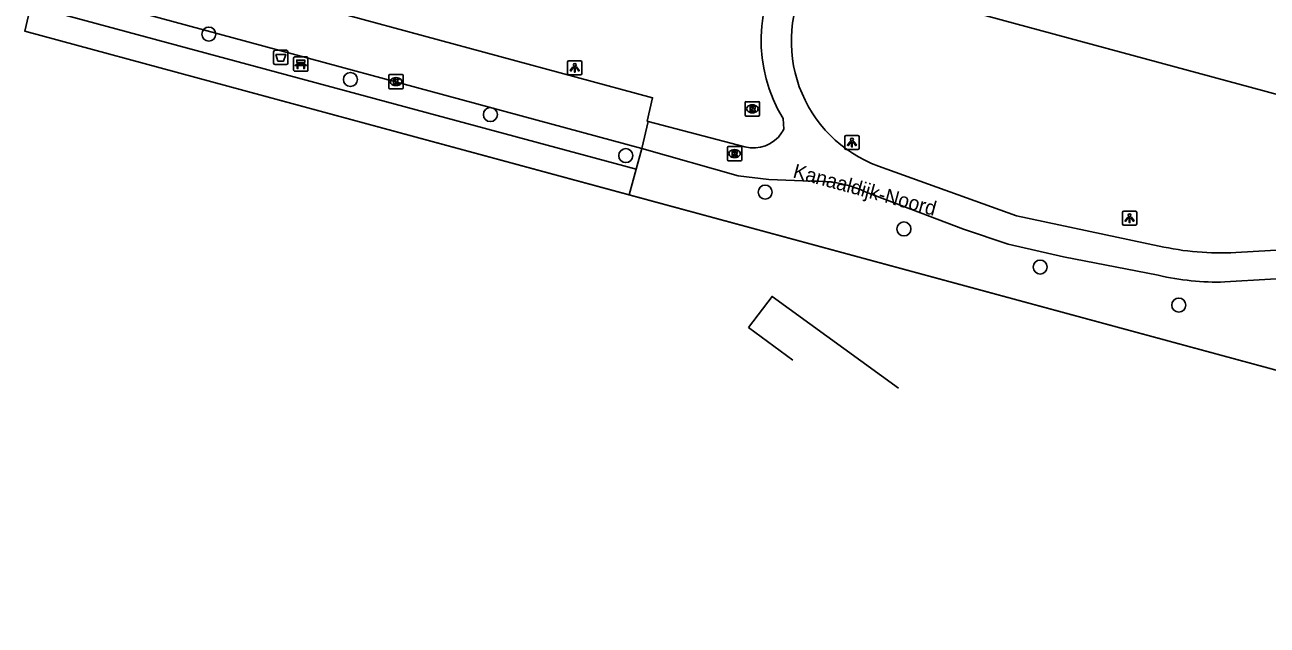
# Model space of a CAD drawing. Extents: x 161772 to 163123, y 383092 to 383917.
# Drawn here: x 161987 to 162073.6, y 383107.9 to 383149.8 of the extents above; entities that cross this region are included whole.
import ezdxf

# ---------------------------------------------------------------- set-up
doc = ezdxf.new("R2010")
doc.units = 0
for name, color, linetype in [('IMGEO_Afvalbak', 7, 'Continuous'), ('IMGEO_Bank', 7, 'Continuous'), ('IMGEO_Boom', 7, 'Continuous'), ('IMGEO_Kademuur', 7, 'Continuous'), ('IMGEO_Kolk', 7, 'Continuous'), ('IMGEO_Lichtpunt', 7, 'Continuous'), ('IMGEO_Openbare_ruimte_label', 7, 'Continuous'), ('IMGEO_Pand', 7, 'Continuous'), ('IMGEO_Rioolput', 7, 'Continuous'), ('IMGEO_Voetpad_halfverhard', 7, 'Continuous'), ('IMGEO_Voetpad_open', 7, 'Continuous'), ('IMGEO_Waterloop', 7, 'Continuous')]:
    doc.layers.add(name, color=color, linetype=linetype)

msp = doc.modelspace()

# ---------------------------------------------------------------- linework, layer by layer
at = {"layer": 'IMGEO_Afvalbak'}
for p, q in [((162004.321, 383147.103), (162004.321, 383147.903)), ((162004.321, 383147.903), (162004.321, 383147.103)), ((162004.421, 383148.003), (162005.211, 383148.003)), ((162005.211, 383148.003), (162004.421, 383148.003)), ((162005.311, 383147.903), (162005.311, 383147.103)), ((162005.311, 383147.103), (162005.311, 383147.903)), ((162005.211, 383147.003), (162004.421, 383147.003)), ((162004.421, 383147.003), (162005.211, 383147.003))]:
    msp.add_line(p, q, dxfattribs=at)
msp.add_lwpolyline([(162004.464, 383147.717), (162005.168, 383147.717), (162005.019, 383147.247), (162004.613, 383147.247), (162004.464, 383147.717)], dxfattribs=at)
for centre, start, end in [((162004.421, 383147.903), 90, 180), ((162004.421, 383147.903), 90, 180), ((162005.211, 383147.903), 0, 90), ((162005.211, 383147.903), 360, 90), ((162004.421, 383147.103), 180, 270), ((162004.421, 383147.103), 180, 270), ((162005.211, 383147.103), 270, 0), ((162005.211, 383147.103), 270, 0)]:
    msp.add_arc(centre, 0.1, start, end, dxfattribs=at)
at = {"layer": 'IMGEO_Bank'}
for p, q in [((162005.789, 383147.542), (162006.63, 383147.542)), ((162006.63, 383147.542), (162005.789, 383147.542)), ((162006.714, 383147.467), (162006.714, 383146.626)), ((162006.714, 383146.626), (162006.714, 383147.467)), ((162005.714, 383146.617), (162005.714, 383147.458)), ((162005.714, 383147.458), (162005.714, 383146.617)), ((162006.411, 383146.94), (162006.018, 383146.94)), ((162006.023, 383147.048), (162006.023, 383147.154)), ((162006.067, 383147.154), (162006.067, 383147.048)), ((162006.355, 383147.16), (162006.073, 383147.16)), ((162006.073, 383147.042), (162006.355, 383147.042)), ((162006.361, 383147.048), (162006.361, 383147.154)), ((162006.405, 383147.154), (162006.405, 383147.048)), ((162006.639, 383146.542), (162005.798, 383146.542)), ((162005.798, 383146.542), (162006.639, 383146.542))]:
    msp.add_line(p, q, dxfattribs=at)
for points in [[(162005.961, 383146.94), (162005.819, 383146.94), (162005.931, 383147.042), (162006.017, 383147.042)], [(162006.017, 383147.16), (162005.931, 383147.16), (162005.931, 383147.321), (162006.494, 383147.321), (162006.494, 383147.16), (162006.411, 383147.16)], [(162006.011, 383146.933), (162006.011, 383146.726), (162005.968, 383146.726), (162005.968, 383146.933)], [(162006.411, 383147.042), (162006.494, 383147.042), (162006.606, 383146.94), (162006.467, 383146.94)], [(162006.461, 383146.933), (162006.461, 383146.726), (162006.417, 383146.726), (162006.417, 383146.933)]]:
    msp.add_lwpolyline(points, dxfattribs=at)
for centre, radius, start, end in [((162005.792, 383147.464), 0.0779, 92.4484, 184.28452), ((162005.792, 383147.464), 0.0779, 92.4484, 184.28452), ((162006.636, 383147.464), 0.0779, 2.4484, 94.28452), ((162006.636, 383147.464), 0.0779, 2.4484, 94.28452), ((162005.792, 383146.62), 0.0779, 182.4484, 274.28452), ((162005.792, 383146.62), 0.0779, 182.4484, 274.28452), ((162005.961, 383146.933), 0.00671, 2.89567, 87.10433), ((162006.018, 383146.933), 0.00671, 92.89567, 177.10433), ((162006.016, 383147.153), 0.00671, 2.89567, 87.10433), ((162006.016, 383147.049), 0.00671, 272.89567, 357.10433), ((162006.073, 383147.153), 0.00671, 92.89567, 177.10433), ((162006.073, 383147.049), 0.00671, 182.89567, 267.10433), ((162006.355, 383147.153), 0.00671, 2.89567, 87.10433), ((162006.355, 383147.049), 0.00671, 272.89567, 357.10433), ((162006.412, 383147.153), 0.00671, 92.89567, 177.10433), ((162006.412, 383147.049), 0.00671, 182.89567, 267.10433), ((162006.41, 383146.933), 0.00671, 2.89567, 87.10433), ((162006.467, 383146.933), 0.00671, 92.89567, 177.10433), ((162006.636, 383146.62), 0.0779, 272.4484, 4.28452), ((162006.636, 383146.62), 0.0779, 272.4484, 4.28452)]:
    msp.add_arc(centre, radius, start, end, dxfattribs=at)
at = {"layer": 'IMGEO_Boom'}
for centre in [(161999.799, 383149.13), (162009.672, 383145.967), (162019.431, 383143.518), (162028.874, 383140.66), (162038.592, 383138.117), (162048.27, 383135.548), (162057.766, 383132.895), (162067.433, 383130.242)]:
    msp.add_circle(centre, 0.489, dxfattribs=at)
at = {"layer": 'IMGEO_Kademuur'}
msp.add_lwpolyline([(162139.881, 383107.934), (162112.481, 383115.352), (162000, 383145.804), (161986.972, 383149.331), (161990.33, 383163.776)], dxfattribs=at)
at = {"layer": 'IMGEO_Kolk'}
for p, q in [((162012.351, 383145.391), (162012.351, 383146.243)), ((162012.426, 383146.317), (162013.278, 383146.317)), ((162012.839, 383146.097), (162012.864, 383146.097)), ((162013.352, 383146.243), (162013.352, 383145.391)), ((162013.278, 383145.317), (162012.426, 383145.317)), ((162012.862, 383145.537), (162012.837, 383145.537))]:
    msp.add_line(p, q, dxfattribs=at)
for points in [[(162012.351, 383145.391), (162012.351, 383146.243)], [(162012.426, 383146.317), (162013.278, 383146.317)], [(162012.672, 383146.017), (162012.795, 383146.017), (162012.795, 383145.866), (162012.925, 383146.017), (162013.089, 383146.017), (162012.943, 383145.866), (162013.096, 383145.617), (162012.944, 383145.617), (162012.859, 383145.781), (162012.795, 383145.714), (162012.795, 383145.617), (162012.672, 383145.617), (162012.672, 383146.017)], [(162013.352, 383146.243), (162013.352, 383145.391)], [(162013.278, 383145.317), (162012.426, 383145.317)]]:
    msp.add_lwpolyline(points, dxfattribs=at)
for centre, start, end in [((162012.428, 383146.241), 91.55205, 178.44795), ((162012.428, 383146.241), 91.55205, 178.44795), ((162013.276, 383146.241), 1.55205, 88.44795), ((162013.276, 383146.241), 1.55205, 88.44795), ((162012.428, 383145.393), 181.55205, 268.44795), ((162012.428, 383145.393), 181.55205, 268.44795), ((162013.276, 383145.393), 271.55205, 358.44795), ((162013.276, 383145.393), 271.55205, 358.44795)]:
    msp.add_arc(centre, 0.0765, start, end, dxfattribs=at)
for centre, major_axis, ratio, start_param, end_param in [((162012.838, 383145.817), (-0.387, 0.002), 0.722429, 4.712389, 7.853982), ((162012.863, 383145.817), (-0.39, 0.002), 0.717154, 1.570796, 4.712389)]:
    msp.add_ellipse(centre, major_axis=major_axis, ratio=ratio, start_param=start_param, end_param=end_param, dxfattribs=at)
at = {"layer": 'IMGEO_Lichtpunt'}
for p, q in [((162024.818, 383147.184), (162024.818, 383146.377)), ((162024.818, 383147.184), (162024.818, 383146.377)), ((162025.72, 383147.279), (162024.912, 383147.279)), ((162025.72, 383147.279), (162024.912, 383147.279)), ((162025.814, 383146.377), (162025.814, 383147.184)), ((162025.814, 383146.377), (162025.814, 383147.184)), ((162024.912, 383146.283), (162025.72, 383146.283)), ((162024.912, 383146.283), (162025.72, 383146.283)), ((162044.145, 383141.978), (162044.145, 383141.171)), ((162044.145, 383141.978), (162044.145, 383141.171)), ((162045.047, 383142.073), (162044.239, 383142.073)), ((162045.047, 383142.073), (162044.239, 383142.073)), ((162045.141, 383141.171), (162045.141, 383141.978)), ((162045.141, 383141.171), (162045.141, 383141.978)), ((162044.239, 383141.077), (162045.047, 383141.077)), ((162044.239, 383141.077), (162045.047, 383141.077)), ((162063.503, 383136.704), (162063.503, 383135.897)), ((162063.503, 383136.704), (162063.503, 383135.897)), ((162064.405, 383136.799), (162063.597, 383136.799)), ((162064.405, 383136.799), (162063.597, 383136.799)), ((162064.499, 383135.897), (162064.499, 383136.704)), ((162064.499, 383135.897), (162064.499, 383136.704)), ((162063.597, 383135.803), (162064.405, 383135.803)), ((162063.597, 383135.803), (162064.405, 383135.803))]:
    msp.add_line(p, q, dxfattribs=at)
for points in [[(162025.192, 383146.848), (162025.231, 383146.82), (162025.043, 383146.558), (162025.005, 383146.585), (162025.192, 383146.848)], [(162025.294, 383146.8), (162025.341, 383146.8), (162025.341, 383146.478), (162025.294, 383146.478), (162025.294, 383146.8)], [(162025.404, 383146.82), (162025.442, 383146.847), (162025.629, 383146.585), (162025.59, 383146.557), (162025.404, 383146.82)], [(162044.519, 383141.642), (162044.558, 383141.614), (162044.37, 383141.352), (162044.332, 383141.379), (162044.519, 383141.642)], [(162044.621, 383141.594), (162044.668, 383141.594), (162044.668, 383141.272), (162044.621, 383141.272), (162044.621, 383141.594)], [(162044.731, 383141.614), (162044.769, 383141.641), (162044.956, 383141.379), (162044.917, 383141.351), (162044.731, 383141.614)], [(162063.877, 383136.368), (162063.916, 383136.34), (162063.728, 383136.078), (162063.69, 383136.105), (162063.877, 383136.368)], [(162063.979, 383136.32), (162064.026, 383136.32), (162064.026, 383135.998), (162063.979, 383135.998), (162063.979, 383136.32)], [(162064.089, 383136.34), (162064.127, 383136.367), (162064.314, 383136.105), (162064.275, 383136.077), (162064.089, 383136.34)]]:
    msp.add_lwpolyline(points, dxfattribs=at)
for centre in [(162025.317, 383146.982), (162044.644, 383141.776), (162064.002, 383136.502)]:
    msp.add_circle(centre, 0.0994, dxfattribs=at)
for centre, start, end in [((162024.912, 383147.184), 90, 180), ((162024.912, 383147.184), 90, 180), ((162025.72, 383147.184), 0, 90), ((162025.72, 383147.184), 0, 90), ((162024.912, 383146.377), 180, 270), ((162024.912, 383146.377), 180, 270), ((162025.72, 383146.377), 270, 0), ((162025.72, 383146.377), 270, 360), ((162044.239, 383141.978), 90, 180), ((162044.239, 383141.978), 90, 180), ((162045.047, 383141.978), 0, 90), ((162045.047, 383141.978), 0, 90), ((162044.239, 383141.171), 180, 270), ((162044.239, 383141.171), 180, 270), ((162045.047, 383141.171), 270, 0), ((162045.047, 383141.171), 270, 360), ((162063.597, 383136.704), 90, 180), ((162063.597, 383136.704), 90, 180), ((162064.405, 383136.704), 0, 90), ((162064.405, 383136.704), 0, 90), ((162063.597, 383135.897), 180, 270), ((162063.597, 383135.897), 180, 270), ((162064.405, 383135.897), 270, 0), ((162064.405, 383135.897), 270, 360)]:
    msp.add_arc(centre, 0.0946, start, end, dxfattribs=at)
at = {"layer": 'IMGEO_Pand'}
msp.add_lwpolyline([(162090.04, 383147.373), (162088.311, 383141.123), (162051.363, 383151.118), (162045.642, 383156.284)], dxfattribs=at)
at = {"layer": 'IMGEO_Rioolput'}
for p, q in [((162037.199, 383143.495), (162037.199, 383144.347)), ((162037.274, 383144.421), (162038.126, 383144.421)), ((162037.687, 383144.201), (162037.712, 383144.201)), ((162038.2, 383144.347), (162038.2, 383143.495)), ((162038.126, 383143.421), (162037.274, 383143.421)), ((162037.71, 383143.641), (162037.685, 383143.641)), ((162035.959, 383140.373), (162035.959, 383141.225)), ((162036.034, 383141.299), (162036.886, 383141.299)), ((162036.447, 383141.079), (162036.472, 383141.079)), ((162036.96, 383141.225), (162036.96, 383140.373)), ((162036.886, 383140.299), (162036.034, 383140.299)), ((162036.47, 383140.519), (162036.445, 383140.519))]:
    msp.add_line(p, q, dxfattribs=at)
for points in [[(162037.199, 383143.495), (162037.199, 383144.347)], [(162037.274, 383144.421), (162038.126, 383144.421)], [(162037.788, 383144.119), (162037.536, 383144.121), (162037.536, 383143.721)], [(162037.714, 383144.04), (162037.66, 383144.04), (162037.66, 383143.959)], [(162038.2, 383144.347), (162038.2, 383143.495)], [(162038.126, 383143.421), (162037.274, 383143.421)], [(162037.536, 383143.721), (162037.66, 383143.721), (162037.66, 383143.883), (162037.671, 383143.883)], [(162037.66, 383143.959), (162037.712, 383143.959)], [(162037.718, 383143.854), (162037.789, 383143.721), (162037.929, 383143.721), (162037.864, 383143.847)], [(162035.959, 383140.373), (162035.959, 383141.225)], [(162036.034, 383141.299), (162036.886, 383141.299)], [(162036.548, 383140.997), (162036.296, 383140.999), (162036.296, 383140.599)], [(162036.296, 383140.599), (162036.42, 383140.599), (162036.42, 383140.761), (162036.431, 383140.761)], [(162036.474, 383140.918), (162036.42, 383140.918), (162036.42, 383140.837)], [(162036.42, 383140.837), (162036.472, 383140.837)], [(162036.478, 383140.732), (162036.549, 383140.599), (162036.689, 383140.599), (162036.624, 383140.725)], [(162036.96, 383141.225), (162036.96, 383140.373)], [(162036.886, 383140.299), (162036.034, 383140.299)]]:
    msp.add_lwpolyline(points, dxfattribs=at)
for centre, radius, start, end in [((162037.276, 383144.345), 0.0765, 91.55205, 178.44795), ((162037.276, 383144.345), 0.0765, 91.55205, 178.44795), ((162037.72, 383143.944), 0.0964, 77.00612, 93.18647), ((162037.734, 383144.001), 0.0378, 276.66336, 79.67722), ((162037.787, 383144.009), 0.109, 350.36119, 89.41601), ((162038.124, 383144.345), 0.0765, 1.55205, 88.44795), ((162038.124, 383144.345), 0.0765, 1.55205, 88.44795), ((162037.276, 383143.497), 0.0765, 181.55205, 268.44795), ((162037.276, 383143.497), 0.0765, 181.55205, 268.44795), ((162037.67, 383143.83), 0.0533, 26.02933, 88.69889), ((162037.696, 383144.148), 0.19, 274.7715, 282.96867), ((162037.785, 383144.009), 0.112, 277.58423, 350.98172), ((162037.769, 383143.794), 0.108, 29.51342, 73.79051), ((162038.124, 383143.497), 0.0765, 271.55205, 358.44795), ((162038.124, 383143.497), 0.0765, 271.55205, 358.44795), ((162036.036, 383141.223), 0.0765, 91.55205, 178.44795), ((162036.036, 383141.223), 0.0765, 91.55205, 178.44795), ((162036.43, 383140.708), 0.0533, 26.02933, 88.69889), ((162036.456, 383141.026), 0.19, 274.7715, 282.96867), ((162036.48, 383140.822), 0.0964, 77.00612, 93.18647), ((162036.494, 383140.879), 0.0378, 276.66336, 79.67722), ((162036.547, 383140.887), 0.109, 350.36119, 89.41601), ((162036.545, 383140.887), 0.112, 277.58423, 350.98172), ((162036.529, 383140.672), 0.108, 29.51342, 73.79051), ((162036.884, 383141.223), 0.0765, 1.55205, 88.44795), ((162036.884, 383141.223), 0.0765, 1.55205, 88.44795), ((162036.036, 383140.375), 0.0765, 181.55205, 268.44795), ((162036.036, 383140.375), 0.0765, 181.55205, 268.44795), ((162036.884, 383140.375), 0.0765, 271.55205, 358.44795), ((162036.884, 383140.375), 0.0765, 271.55205, 358.44795)]:
    msp.add_arc(centre, radius, start, end, dxfattribs=at)
for centre, major_axis, ratio, start_param, end_param in [((162037.686, 383143.921), (-0.387, 0.002), 0.722429, 4.712389, 7.853982), ((162037.711, 383143.921), (-0.39, 0.002), 0.717154, 1.570796, 4.712389), ((162036.446, 383140.799), (-0.387, 0.002), 0.722429, 4.712389, 7.853982), ((162036.471, 383140.799), (-0.39, 0.002), 0.717154, 1.570796, 4.712389)]:
    msp.add_ellipse(centre, major_axis=major_axis, ratio=ratio, start_param=start_param, end_param=end_param, dxfattribs=at)
at = {"layer": 'IMGEO_Voetpad_halfverhard'}
for points in [[(162039.885, 383142.498), (162039.84, 383143.252)], [(162030.436, 383143.05), (162037.183, 383141.264)], [(162029.99, 383141.153), (162036.722, 383139.246), (162038.857, 383138.988), (162041.82, 383138.869)], [(162046.488, 383139.931), (162056.112, 383136.468), (162066.058, 383134.358)], [(162045.741, 383138.063), (162052.434, 383135.532), (162055.538, 383134.499), (162059.4, 383133.607), (162065.999, 383132.323)], [(162071.411, 383133.9), (162082.709, 383134.559), (162092.017, 383135.492)], [(162070.646, 383131.858), (162083.389, 383132.602)]]:
    msp.add_lwpolyline(points, dxfattribs=at)
for centre, radius, start, end in [((162048.714, 383148.683), 10.404, 145.55715, 211.46606), ((162049.675, 383148.624), 9.259, 150.17617, 249.8689), ((162037.757, 383143.565), 2.38, 326.49431, 333.36853), ((162037.772, 383143.549), 2.36, 255.55732, 326.62569), ((162042.168, 383130.619), 8.257, 64.35571, 92.41248), ((162070.406, 383153.664), 19.789, 257.30805, 272.91137), ((162070.076, 383149.617), 17.768, 256.73403, 271.83746)]:
    msp.add_arc(centre, radius, start, end, dxfattribs=at)
at = {"layer": 'IMGEO_Voetpad_open'}
for points in [[(162029.599, 383139.708), (161989.17, 383150.608), (161993.46, 383166.979), (161994.894, 383166.648), (161991.014, 383151.724), (162029.99, 383141.153)], [(162029.115, 383137.922), (162000, 383145.804), (161986.972, 383149.331), (161990.33, 383163.776)], [(162004.126, 383151.906), (162030.739, 383144.691), (162030.366, 383143.069), (162030.436, 383143.05)], [(162030.436, 383143.05), (162029.99, 383141.153)], [(162029.99, 383141.153), (162029.599, 383139.708)], [(162029.599, 383139.708), (162029.115, 383137.922)]]:
    msp.add_lwpolyline(points, dxfattribs=at)
at = {"layer": 'IMGEO_Waterloop'}
for points in [[(162112.481, 383115.352), (162029.115, 383137.922)], [(162037.424, 383128.677), (162039.073, 383130.851), (162047.886, 383124.46)], [(162040.518, 383126.413), (162037.424, 383128.677)]]:
    msp.add_lwpolyline(points, dxfattribs=at)

# ---------------------------------------------------------------- texts
at = {"layer": 'IMGEO_Openbare_ruimte_label'}
msp.add_text('Kanaaldijk-Noord', height=1, rotation=344.81021, dxfattribs=at).set_placement((162040.469, 383139.149))

doc.saveas('drawing.dxf')
